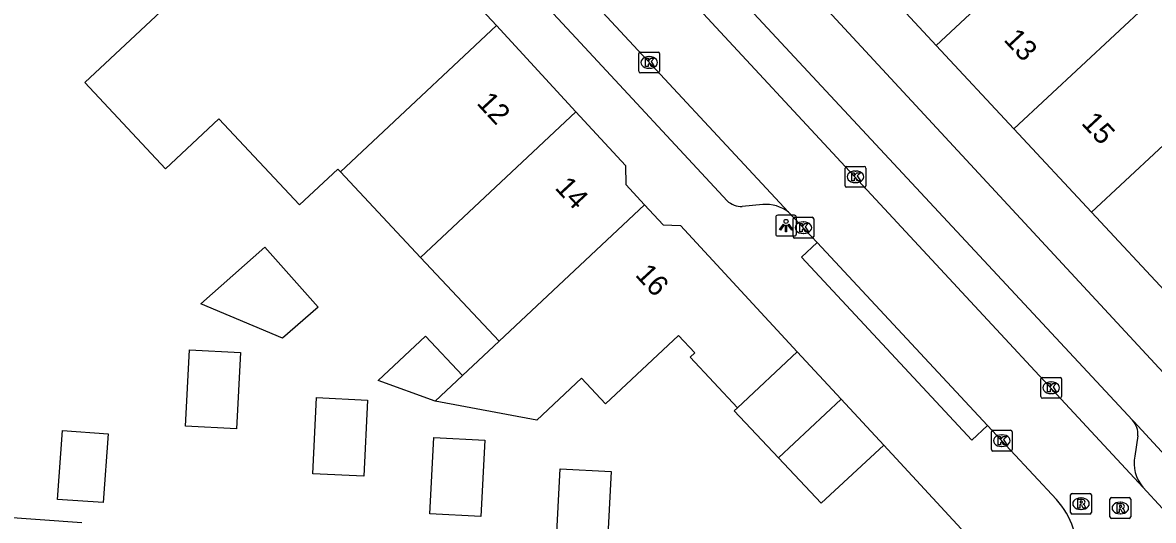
# Model space of a CAD drawing. Extents: x 159961 to 160856, y 382704 to 383353.
# Drawn here: x 160679.3 to 160733.9, y 382970.6 to 382994.6 of the extents above; entities that cross this region are included whole.
import ezdxf

# ---------------------------------------------------------------- set-up
doc = ezdxf.new("R2010")
doc.units = 0
for name, color, linetype in [('IMGEO_Kolk', 7, 'Continuous'), ('IMGEO_Lichtpunt', 7, 'Continuous'), ('IMGEO_Muur', 7, 'Continuous'), ('IMGEO_Pand', 7, 'Continuous'), ('IMGEO_Pand_nummerreeks', 7, 'Continuous'), ('IMGEO_Rijbaan_lokaal_open', 7, 'Continuous'), ('IMGEO_Rioolput', 7, 'Continuous'), ('IMGEO_Voetpad_open', 7, 'Continuous')]:
    doc.layers.add(name, color=color, linetype=linetype)

msp = doc.modelspace()

# ---------------------------------------------------------------- linework, layer by layer
at = {"layer": 'IMGEO_Kolk'}
for p, q in [((160709.033, 382992.249), (160709.033, 382993.101)), ((160709.108, 382993.175), (160709.96, 382993.175)), ((160709.521, 382992.955), (160709.546, 382992.955)), ((160710.034, 382993.101), (160710.034, 382992.249)), ((160709.96, 382992.175), (160709.108, 382992.175)), ((160709.544, 382992.395), (160709.519, 382992.395)), ((160718.987, 382986.732), (160718.987, 382987.584)), ((160719.062, 382987.658), (160719.914, 382987.658)), ((160719.475, 382987.438), (160719.5, 382987.438)), ((160719.988, 382987.584), (160719.988, 382986.732)), ((160719.498, 382986.878), (160719.473, 382986.878)), ((160719.914, 382986.658), (160719.062, 382986.658)), ((160716.476, 382984.28), (160716.476, 382985.132)), ((160716.551, 382985.206), (160717.403, 382985.206)), ((160717.477, 382985.132), (160717.477, 382984.28)), ((160716.964, 382984.986), (160716.989, 382984.986)), ((160717.403, 382984.206), (160716.551, 382984.206)), ((160716.987, 382984.426), (160716.962, 382984.426)), ((160728.511, 382977.484), (160729.363, 382977.484)), ((160728.436, 382976.558), (160728.436, 382977.41)), ((160728.924, 382977.264), (160728.949, 382977.264)), ((160729.437, 382977.41), (160729.437, 382976.558)), ((160729.363, 382976.484), (160728.511, 382976.484)), ((160728.947, 382976.704), (160728.922, 382976.704)), ((160726.05, 382974.008), (160726.05, 382974.86)), ((160726.125, 382974.934), (160726.977, 382974.934)), ((160726.538, 382974.714), (160726.563, 382974.714)), ((160727.051, 382974.86), (160727.051, 382974.008)), ((160726.561, 382974.154), (160726.536, 382974.154)), ((160726.977, 382973.934), (160726.125, 382973.934))]:
    msp.add_line(p, q, dxfattribs=at)
for points in [[(160709.033, 382992.249), (160709.033, 382993.101)], [(160709.108, 382993.175), (160709.96, 382993.175)], [(160709.354, 382992.875), (160709.477, 382992.875), (160709.477, 382992.724), (160709.607, 382992.875), (160709.771, 382992.875), (160709.625, 382992.724), (160709.778, 382992.475), (160709.626, 382992.475), (160709.541, 382992.639), (160709.477, 382992.572), (160709.477, 382992.475), (160709.354, 382992.475), (160709.354, 382992.875)], [(160710.034, 382993.101), (160710.034, 382992.249)], [(160709.96, 382992.175), (160709.108, 382992.175)], [(160718.987, 382986.732), (160718.987, 382987.584)], [(160719.062, 382987.658), (160719.914, 382987.658)], [(160719.308, 382987.358), (160719.431, 382987.358), (160719.431, 382987.207), (160719.561, 382987.358), (160719.725, 382987.358), (160719.579, 382987.207), (160719.732, 382986.958), (160719.58, 382986.958), (160719.495, 382987.122), (160719.431, 382987.055), (160719.431, 382986.958), (160719.308, 382986.958), (160719.308, 382987.358)], [(160719.988, 382987.584), (160719.988, 382986.732)], [(160719.914, 382986.658), (160719.062, 382986.658)], [(160716.476, 382984.28), (160716.476, 382985.132)], [(160716.551, 382985.206), (160717.403, 382985.206)], [(160717.477, 382985.132), (160717.477, 382984.28)], [(160716.797, 382984.906), (160716.92, 382984.906), (160716.92, 382984.755), (160717.05, 382984.906), (160717.214, 382984.906), (160717.068, 382984.755), (160717.221, 382984.506), (160717.069, 382984.506), (160716.984, 382984.67), (160716.92, 382984.603), (160716.92, 382984.506), (160716.797, 382984.506), (160716.797, 382984.906)], [(160717.403, 382984.206), (160716.551, 382984.206)], [(160728.511, 382977.484), (160729.363, 382977.484)], [(160728.436, 382976.558), (160728.436, 382977.41)], [(160728.757, 382977.184), (160728.88, 382977.184), (160728.88, 382977.033), (160729.01, 382977.184), (160729.174, 382977.184), (160729.028, 382977.033), (160729.181, 382976.784), (160729.029, 382976.784), (160728.944, 382976.948), (160728.88, 382976.881), (160728.88, 382976.784), (160728.757, 382976.784), (160728.757, 382977.184)], [(160729.437, 382977.41), (160729.437, 382976.558)], [(160729.363, 382976.484), (160728.511, 382976.484)], [(160726.05, 382974.008), (160726.05, 382974.86)], [(160726.125, 382974.934), (160726.977, 382974.934)], [(160727.051, 382974.86), (160727.051, 382974.008)], [(160726.371, 382974.634), (160726.494, 382974.634), (160726.494, 382974.483), (160726.624, 382974.634), (160726.788, 382974.634), (160726.642, 382974.483), (160726.795, 382974.234), (160726.643, 382974.234), (160726.558, 382974.398), (160726.494, 382974.331), (160726.494, 382974.234), (160726.371, 382974.234), (160726.371, 382974.634)], [(160726.977, 382973.934), (160726.125, 382973.934)]]:
    msp.add_lwpolyline(points, dxfattribs=at)
for centre, start, end in [((160709.11, 382993.099), 91.552, 178.448), ((160709.11, 382993.099), 91.552, 178.448), ((160709.958, 382993.099), 1.552, 88.448), ((160709.958, 382993.099), 1.552, 88.448), ((160709.11, 382992.251), 181.552, 268.448), ((160709.11, 382992.251), 181.552, 268.448), ((160709.958, 382992.251), 271.552, 358.448), ((160709.958, 382992.251), 271.552, 358.448), ((160719.064, 382987.582), 91.552, 178.448), ((160719.064, 382987.582), 91.552, 178.448), ((160719.912, 382987.582), 1.552, 88.448), ((160719.912, 382987.582), 1.552, 88.448), ((160719.064, 382986.734), 181.552, 268.448), ((160719.064, 382986.734), 181.552, 268.448), ((160719.912, 382986.734), 271.552, 358.448), ((160719.912, 382986.734), 271.552, 358.448), ((160716.553, 382985.13), 91.552, 178.448), ((160716.553, 382985.13), 91.552, 178.448), ((160717.401, 382985.13), 1.552, 88.448), ((160717.401, 382985.13), 1.552, 88.448), ((160716.553, 382984.282), 181.552, 268.448), ((160716.553, 382984.282), 181.552, 268.448), ((160717.401, 382984.282), 271.552, 358.448), ((160717.401, 382984.282), 271.552, 358.448), ((160728.513, 382977.408), 91.552, 178.448), ((160728.513, 382977.408), 91.552, 178.448), ((160729.361, 382977.408), 1.552, 88.448), ((160729.361, 382977.408), 1.552, 88.448), ((160728.513, 382976.56), 181.552, 268.448), ((160728.513, 382976.56), 181.552, 268.448), ((160729.361, 382976.56), 271.552, 358.448), ((160729.361, 382976.56), 271.552, 358.448), ((160726.127, 382974.858), 91.552, 178.448), ((160726.127, 382974.858), 91.552, 178.448), ((160726.975, 382974.858), 1.552, 88.448), ((160726.975, 382974.858), 1.552, 88.448), ((160726.127, 382974.01), 181.552, 268.448), ((160726.127, 382974.01), 181.552, 268.448), ((160726.975, 382974.01), 271.552, 358.448), ((160726.975, 382974.01), 271.552, 358.448)]:
    msp.add_arc(centre, 0.0765, start, end, dxfattribs=at)
for centre, major_axis, ratio, start_param, end_param in [((160709.52, 382992.675), (-0.387, 0.002), 0.722429, 4.712389, 7.853982), ((160709.545, 382992.675), (-0.39, 0.002), 0.717154, 1.570796, 4.712389), ((160719.474, 382987.158), (-0.387, 0.002), 0.722429, 4.712389, 7.853982), ((160719.499, 382987.158), (-0.39, 0.002), 0.717154, 1.570796, 4.712389), ((160716.963, 382984.706), (-0.387, 0.002), 0.722429, 4.712389, 7.853982), ((160716.988, 382984.706), (-0.39, 0.002), 0.717154, 1.570796, 4.712389), ((160728.923, 382976.984), (-0.387, 0.002), 0.722429, 4.712389, 7.853982), ((160728.948, 382976.984), (-0.39, 0.002), 0.717154, 1.570796, 4.712389), ((160726.537, 382974.434), (-0.387, 0.002), 0.722429, 4.712389, 7.853982), ((160726.562, 382974.434), (-0.39, 0.002), 0.717154, 1.570796, 4.712389)]:
    msp.add_ellipse(centre, major_axis=major_axis, ratio=ratio, start_param=start_param, end_param=end_param, dxfattribs=at)
at = {"layer": 'IMGEO_Lichtpunt'}
for p, q in [((160715.641, 382985.21), (160715.641, 382984.403)), ((160715.641, 382985.21), (160715.641, 382984.403)), ((160716.543, 382985.305), (160715.735, 382985.305)), ((160716.543, 382985.305), (160715.735, 382985.305)), ((160716.637, 382984.403), (160716.637, 382985.21)), ((160716.637, 382984.403), (160716.637, 382985.21)), ((160715.735, 382984.309), (160716.543, 382984.309)), ((160715.735, 382984.309), (160716.543, 382984.309))]:
    msp.add_line(p, q, dxfattribs=at)
for points in [[(160716.015, 382984.874), (160716.054, 382984.846), (160715.866, 382984.584), (160715.828, 382984.611), (160716.015, 382984.874)], [(160716.117, 382984.826), (160716.164, 382984.826), (160716.164, 382984.504), (160716.117, 382984.504), (160716.117, 382984.826)], [(160716.227, 382984.846), (160716.265, 382984.873), (160716.452, 382984.611), (160716.413, 382984.583), (160716.227, 382984.846)]]:
    msp.add_lwpolyline(points, dxfattribs=at)
msp.add_circle((160716.14, 382985.008), 0.0994, dxfattribs=at)
for centre, start, end in [((160715.735, 382985.21), 90, 180), ((160715.735, 382985.21), 90, 180), ((160716.543, 382985.21), 0, 90), ((160716.543, 382985.21), 0, 90), ((160715.735, 382984.403), 180, 270), ((160715.735, 382984.403), 180, 270), ((160716.543, 382984.403), 270, 0), ((160716.543, 382984.403), 270, 360)]:
    msp.add_arc(centre, 0.0946, start, end, dxfattribs=at)
at = {"layer": 'IMGEO_Muur'}
msp.add_lwpolyline([(160720.853, 382974.209), (160724.596, 382970.181)], dxfattribs=at)
at = {"layer": 'IMGEO_Pand'}
for points in [[(160694.63, 382987.392), (160694.499, 382987.531), (160692.655, 382985.801), (160688.767, 382989.956), (160686.19, 382987.544), (160682.295, 382991.706), (160694.256, 383002.897)], [(160694.256, 383002.897), (160702.157, 382994.453)], [(160731.515, 383001.061), (160730.375, 383000), (160723.39, 382993.5)], [(160723.39, 382993.5), (160719.646, 382997.52)], [(160727.135, 382989.479), (160735.257, 382997.04)], [(160694.63, 382987.392), (160696.201, 382988.866), (160702.157, 382994.453)], [(160702.157, 382994.453), (160705.995, 382990.297)], [(160723.39, 382993.5), (160727.135, 382989.479)], [(160739.001, 382993.018), (160730.879, 382985.458)], [(160698.5, 382983.267), (160705.995, 382990.297)], [(160705.995, 382990.297), (160708.387, 382987.707), (160708.406, 382986.786), (160709.309, 382985.813)], [(160730.879, 382985.458), (160727.135, 382989.479)], [(160698.5, 382983.267), (160694.63, 382987.392)], [(160709.309, 382985.813), (160702.288, 382979.229)], [(160709.309, 382985.813), (160710.214, 382984.848), (160711.038, 382984.809), (160716.681, 382978.726)], [(160730.879, 382985.458), (160734.623, 382981.438)], [(160690.983, 382983.769), (160693.552, 382980.866), (160691.833, 382979.372), (160687.899, 382981.026), (160690.983, 382983.769)], [(160702.288, 382979.229), (160698.5, 382983.267)], [(160699.206, 382976.338), (160696.452, 382977.342), (160698.73, 382979.479), (160700.52, 382977.57)], [(160713.8, 382976.024), (160711.516, 382978.458), (160711.734, 382978.663), (160710.94, 382979.51), (160707.427, 382976.214), (160706.263, 382977.454), (160704.105, 382975.428), (160699.206, 382976.338)], [(160700.52, 382977.57), (160702.288, 382979.229)], [(160689.802, 382978.689), (160689.613, 382975.01), (160687.152, 382975.137), (160687.342, 382978.816), (160689.802, 382978.689)], [(160713.8, 382976.024), (160716.681, 382978.726)], [(160716.681, 382978.726), (160718.793, 382976.44)], [(160699.206, 382976.338), (160700.52, 382977.57)], [(160695.941, 382976.394), (160695.752, 382972.715), (160693.291, 382972.842), (160693.48, 382976.521), (160695.941, 382976.394)], [(160718.793, 382976.44), (160715.77, 382973.604)], [(160718.793, 382976.44), (160720.853, 382974.209)], [(160715.77, 382973.604), (160713.641, 382975.874), (160713.8, 382976.024)], [(160683.411, 382974.77), (160683.18, 382971.444), (160680.98, 382971.597), (160681.212, 382974.923), (160683.411, 382974.77)], [(160701.594, 382974.454), (160701.404, 382970.775), (160698.943, 382970.902), (160699.133, 382974.581), (160701.594, 382974.454)], [(160720.853, 382974.209), (160717.826, 382971.413), (160715.77, 382973.604)], [(160707.694, 382972.943), (160707.504, 382969.264), (160705.043, 382969.391), (160705.233, 382973.07), (160707.694, 382972.943)], [(160676.094, 382970.915), (160682.147, 382970.495)]]:
    msp.add_lwpolyline(points, dxfattribs=at)
at = {"layer": 'IMGEO_Rijbaan_lokaal_open'}
for points in [[(160709.652, 382997.732), (160733.364, 382972.191)], [(160707.076, 382995.331), (160716.257, 382985.452)], [(160717.644, 382983.994), (160716.257, 382985.452)], [(160717.644, 382983.994), (160725.867, 382975.173)], [(160729.198, 382971.599), (160725.867, 382975.173)], [(160733.364, 382972.191), (160734.313, 382971.169)]]:
    msp.add_lwpolyline(points, dxfattribs=at)
msp.add_arc((160725.939, 382968.775), 4.313, 358.1538, 40.9062, dxfattribs=at)
at = {"layer": 'IMGEO_Rioolput'}
for p, q in [((160729.875, 382970.967), (160729.875, 382971.819)), ((160729.95, 382971.893), (160730.802, 382971.893)), ((160730.363, 382971.673), (160730.388, 382971.673)), ((160730.876, 382971.819), (160730.876, 382970.967)), ((160731.773, 382970.76), (160731.773, 382971.612)), ((160731.848, 382971.686), (160732.7, 382971.686)), ((160732.261, 382971.466), (160732.286, 382971.466)), ((160732.774, 382971.612), (160732.774, 382970.76)), ((160730.802, 382970.893), (160729.95, 382970.893)), ((160730.386, 382971.113), (160730.361, 382971.113)), ((160732.284, 382970.906), (160732.259, 382970.906)), ((160732.7, 382970.686), (160731.848, 382970.686))]:
    msp.add_line(p, q, dxfattribs=at)
for points in [[(160729.875, 382970.967), (160729.875, 382971.819)], [(160729.95, 382971.893), (160730.802, 382971.893)], [(160730.464, 382971.591), (160730.212, 382971.593), (160730.212, 382971.193)], [(160730.39, 382971.512), (160730.336, 382971.512), (160730.336, 382971.431)], [(160730.336, 382971.431), (160730.388, 382971.431)], [(160730.876, 382971.819), (160730.876, 382970.967)], [(160731.773, 382970.76), (160731.773, 382971.612)], [(160731.848, 382971.686), (160732.7, 382971.686)], [(160732.774, 382971.612), (160732.774, 382970.76)], [(160730.802, 382970.893), (160729.95, 382970.893)], [(160730.212, 382971.193), (160730.336, 382971.193), (160730.336, 382971.355), (160730.347, 382971.355)], [(160730.394, 382971.326), (160730.465, 382971.193), (160730.605, 382971.193), (160730.54, 382971.319)], [(160732.362, 382971.384), (160732.11, 382971.386), (160732.11, 382970.986)], [(160732.11, 382970.986), (160732.234, 382970.986), (160732.234, 382971.148), (160732.245, 382971.148)], [(160732.288, 382971.305), (160732.234, 382971.305), (160732.234, 382971.224)], [(160732.234, 382971.224), (160732.286, 382971.224)], [(160732.292, 382971.119), (160732.363, 382970.986), (160732.503, 382970.986), (160732.438, 382971.112)], [(160732.7, 382970.686), (160731.848, 382970.686)]]:
    msp.add_lwpolyline(points, dxfattribs=at)
for centre, radius, start, end in [((160729.952, 382971.817), 0.0765, 91.552, 178.448), ((160729.952, 382971.817), 0.0765, 91.552, 178.448), ((160730.372, 382971.62), 0.19, 274.7715, 282.9687), ((160730.396, 382971.416), 0.0964, 77.0061, 93.1865), ((160730.41, 382971.473), 0.0378, 276.6634, 79.6772), ((160730.463, 382971.481), 0.109, 350.3612, 89.416), ((160730.461, 382971.481), 0.112, 277.5842, 350.9817), ((160730.8, 382971.817), 0.0765, 1.552, 88.448), ((160730.8, 382971.817), 0.0765, 1.552, 88.448), ((160731.85, 382971.61), 0.0765, 91.552, 178.448), ((160731.85, 382971.61), 0.0765, 91.552, 178.448), ((160732.698, 382971.61), 0.0765, 1.552, 88.448), ((160732.698, 382971.61), 0.0765, 1.552, 88.448), ((160729.952, 382970.969), 0.0765, 181.552, 268.448), ((160729.952, 382970.969), 0.0765, 181.552, 268.448), ((160730.346, 382971.302), 0.0533, 26.0293, 88.6989), ((160730.445, 382971.266), 0.108, 29.5134, 73.7905), ((160730.8, 382970.969), 0.0765, 271.552, 358.448), ((160730.8, 382970.969), 0.0765, 271.552, 358.448), ((160732.244, 382971.095), 0.0533, 26.0293, 88.6989), ((160732.27, 382971.413), 0.19, 274.7715, 282.9687), ((160732.294, 382971.209), 0.0964, 77.0061, 93.1865), ((160732.308, 382971.266), 0.0378, 276.6634, 79.6772), ((160732.361, 382971.274), 0.109, 350.3612, 89.416), ((160732.359, 382971.274), 0.112, 277.5842, 350.9817), ((160732.343, 382971.059), 0.108, 29.5134, 73.7905), ((160731.85, 382970.762), 0.0765, 181.552, 268.448), ((160731.85, 382970.762), 0.0765, 181.552, 268.448), ((160732.698, 382970.762), 0.0765, 271.552, 358.448), ((160732.698, 382970.762), 0.0765, 271.552, 358.448)]:
    msp.add_arc(centre, radius, start, end, dxfattribs=at)
for centre, major_axis, ratio, start_param, end_param in [((160730.362, 382971.393), (-0.387, 0.002), 0.722429, 4.712389, 7.853982), ((160730.387, 382971.393), (-0.39, 0.002), 0.717154, 1.570796, 4.712389), ((160732.26, 382971.186), (-0.387, 0.002), 0.722429, 4.712389, 7.853982), ((160732.285, 382971.186), (-0.39, 0.002), 0.717154, 1.570796, 4.712389)]:
    msp.add_ellipse(centre, major_axis=major_axis, ratio=ratio, start_param=start_param, end_param=end_param, dxfattribs=at)
at = {"layer": 'IMGEO_Voetpad_open'}
for points in [[(160673.235, 383043.388), (160678.604, 383037.664), (160678.452, 383037.535), (160702.049, 383012.215), (160702.21, 383012.323), (160702.992, 383011.556), (160713.702, 383000), (160739.609, 382972.048), (160740.527, 382971.923)], [(160713.29, 382985.999), (160706.009, 382993.847), (160700.664, 382999.59)], [(160710.24, 382999.711), (160732.864, 382975.416)], [(160715.014, 382985.817), (160714.023, 382985.724)], [(160725.867, 382975.173), (160725.106, 382974.464), (160716.883, 382983.285), (160717.644, 382983.994)], [(160737.877, 382969.993), (160737.869, 382970.007), (160732.93, 382975.365), (160732.864, 382975.416)], [(160724.486, 382968.87), (160724.596, 382970.181), (160720.853, 382974.209)], [(160733.126, 382974.673), (160732.971, 382973.693)]]:
    msp.add_lwpolyline(points, dxfattribs=at)
for centre, radius, start, end in [((160714.017, 382986.822), 1.098, 228.5469, 270.3239), ((160715.186, 382984.105), 1.721, 51.5209, 95.7499), ((160732.085, 382974.724), 1.042, 357.2124, 41.6354), ((160734.686, 382973.339), 1.751, 168.3533, 220.9723)]:
    msp.add_arc(centre, radius, start, end, dxfattribs=at)

# ---------------------------------------------------------------- texts
at = {"layer": 'IMGEO_Pand_nummerreeks'}
for s, rotation, p in [('13', 312.9584, (160726.606, 382993.746)), ('12', 312.7237, (160701.165, 382990.693)), ('15', 312.9584, (160730.35, 382989.725)), ('14', 312.7237, (160704.94, 382986.606)), ('16', 312.7253, (160708.819, 382982.406))]:
    msp.add_text(s, height=1, rotation=rotation, dxfattribs=at).set_placement(p)

doc.saveas('drawing.dxf')
